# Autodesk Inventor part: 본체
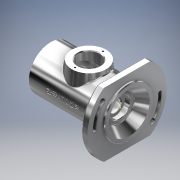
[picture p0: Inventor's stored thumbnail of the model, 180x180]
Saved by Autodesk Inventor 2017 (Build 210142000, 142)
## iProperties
Part Number: 본체
Material: 알루미늄 6061
Document SubType Name: Modeling
Designer: MRC
Density: 2.7 g/cm^3
Appearance: 알루미늄 - 평지
Mass: 686.809 g
Surface Area: 618.883 cm^2
Volume: 254.374 cm^3
Author: MRC
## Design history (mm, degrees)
sketch "스케치1"
  geometry: L1 (47, 33.985)-(47, -33.985); L2 (-47, 33.985)-(-47, -33.985); A1 r 58 centre (0, 0) between (47, 33.985) and (-47, 33.985); A2 r 58 centre (0, 0) between (-47, -33.985) and (47, -33.985); 1 further point
  constraints: 4 end point, 4 point on circle, 2 centre point, 2 vertical, 1 coincident
  dimensions: "d1" = 47 distance from line of point (0, 0) L1; "d2" = 47 distance from line of point (0, 0) L2; "d3" = 58 radius of A2; "d4" = 58 radius of A1
extrude "돌출1" new body sketch "스케치1" distance "d5" = 10; taper "d6" = 0 deg
sketch "스케치2"
  geometry: C1 r 32 at (0, 0); 1 further point
  constraints: 1 centre point, 1 coincident
  dimensions: "d7" = 64 diameter of C1
extrude "돌출2" join sketch "스케치2" distance "d8" = 102; taper "d9" = 0 deg
node "작업 평면1"
sketch "스케치3"
  geometry: L1 (0, 33.985)-(0, -33.985) reference; L2 (102, -32)-(102, 32) reference; C1 r 25 at (46, 0); 2 further points
  constraints: 1 centre point, 1 horizontal alignment, 1 midpoint
  dimensions: "d11" = 50 diameter of C1; "d12" = 56 distance from line of C1.centre L2
extrude "돌출3" join sketch "스케치3" stored distance "d13" = 102; taper "d14" = 5 deg
sketch "스케치4"
  geometry: C1 r 36 at (0, 0); 1 further point
  constraints: 1 centre point, 1 coincident
  dimensions: "d15" = 72 diameter of C1
extrude "돌출4" join sketch "스케치4" distance "d16" = 3; taper "d17" = 0 deg
sketch "스케치5"
  geometry: L1 (-102, 32)-(-102, -32) reference; L2 (-102, 0)-(13, 0); L3 (13, -36)-(13, 36) reference; L4 (-102, 0)-(-102, 22.5); L5 (-102, 22.5)-(-94, 22.5); L6 (-94, 22.5)-(-94, 24); L7 (-94, 24)-(-91, 24); L8 (-91, 24)-(-91, 22.5); L9 (-91, 22.5)-(-80, 22.5); L10 (-80, 22.5)-(-80, 17.5); L11 (-80, 17.5)-(-77.75, 17.5); L12 (-76, 17.5)-(-76, 18.5); L13 (-77.75, 18.5)-(-77.75, 17.5); L14 (-76, 17.5)-(-65, 17.5); L15 (-65, 17.5)-(-65, 27); L16 (-65, 27)-(-27, 27); L17 (-27, 27)-(-27, 17.5); L18 (-27, 17.5)-(-16, 17.5); L19 (-16, 17.5)-(-16, 15); L20 (-16, 15)-(-11, 15); L21 (-11, 15)-(-11, 11); L22 (-11, 11)-(-8.3, 11); L23 (-8.3, 11)-(-8.3, 15); L24 (-1, 15)-(-1, 20); L25 (-1, 20)-(13, 30); L26 (13, 30)-(13, 0); L27 (-76, 18.5)-(-77.75, 18.5); L28 (-8.3, 15)-(-1, 15); 1 further point
  constraints: 52 end point, 15 perpendicular, 5 point on line, 3 horizontal, 2 midpoint, 1 parallel
  dimensions: "d18" = 45 diameter of L5 L2; "d19" = 48 diameter of L7 L2; "d20" = 45 diameter of L9 L2; "d21" = 37 diameter of L27 L2; "d22" = 35 diameter of L11 L2; "d23" = 54 diameter of L16 L2; "d24" = 30 diameter of L20 L2; "d25" = 22 diameter of L22 L2; "d26" = 30 diameter of L28 L2; "d27" = 40 diameter of L24.end L2; "d28" = 60 diameter of L25.end L2; "d29" = 8 distance of L4.end L5.end; "d30" = 3 distance of L6.end L7.end; "d31" = 22 distance between parallel lines of L10 L4; "d33" = 38 distance of L15.end L16.end; "d34" = 11 distance of L17.end L18.end; "d35" = 5 distance of L19.end L20.end; "d36" = 14 horizontal distance of L24.end L25.end; "d38" = 1.75 distance of L12.end L13.start; "d39" = 7.3 distance of L23.end L24.start; "d128" = 4 distance between parallel lines of L12 L10; "d129" = 11 distance of L12.start L14.end; "d130" = 2.25 distance of L10.end L11.end
revolve "회전1" sketch "스케치5" stored, may be unused: angle "d40" = 90 deg
sketch "스케치6"
  geometry: 1 further point
feature "스레드1" dims "d41" = 10, "d42" = 0
sketch "스케치7"
  geometry: C1 r 25 at (0, 0) reference; C2 r 16 at (0, 0); 1 further point
  constraints: 1 centre point, 1 coincident
  dimensions: "d43" = 32 diameter of C2
extrude "돌출5" cut sketch "스케치7" distance "d44" = 30; taper "d45" = 0 deg
sketch "스케치8"
  geometry: L1 (0, 0)-(36.77, 30.854); L2 (0, 0)-(48, 0); L3 (0, 0)-(-36.77, -30.854); A1 r 48 centre (0, 0) between (36.77, 30.854) and (48, 0); A2 r 4 centre (36.77, 30.854) between (40.58, 29.636) and (37.033, 26.862); A3 r 4 centre (-36.77, -30.854) between (-40.58, -29.636) and (-37.033, -26.862); A4 r 2.25 centre (-48, 0) between (-45.75, 0) and (-50.25, 0); A5 r 4 centre (-48, 0) between (-44, 0) and (-52, 0); A6 r 4 centre (48, 0) between (44, 0) and (52, 0); A7 r 2.25 centre (48, 0) between (45.75, 0) and (50.25, 0); A8 r 52 centre (0, 0) between (52, 0) and (39.834, 33.425); A9 r 52 centre (0, 0) between (-52, 0) and (-39.834, -33.425); A10 r 50.25 centre (0, 0) between (50.25, 0) and (40.58, 29.636); A11 r 50.25 centre (0, 0) between (-50.25, 0) and (-40.58, -29.636); A12 r 45.75 centre (0, 0) between (45.75, 0) and (37.033, 26.862); A13 r 45.75 centre (0, 0) between (-45.75, 0) and (-37.033, -26.862); A14 r 44 centre (0, 0) between (44, 0) and (33.706, 28.283); A15 r 44 centre (0, 0) between (-44, 0) and (-33.706, -28.283); 1 further point
  constraints: 36 point on circle, 15 centre point, 6 coincident, 6 end point, 1 collinear, 1 horizontal, 1 horizontal alignment
  dimensions: "d46" = 96 diameter of A1; "d47" = 40 deg angle of L2 L1; "d48" = 8 diameter of A2; "d49" = 8 diameter of A3; "d72" = 4.5 diameter of A4; "d73" = 8 diameter of A5; "d74" = 8 diameter of A6; "d75" = 4.5 diameter of A7; "d76" = 52 radius of A8; "d77" = 50.25 radius of A10; "d78" = 45.75 radius of A12; "d79" = 44 radius of A14; "d80" = 44 radius of A15; "d81" = 45.75 radius of A13; "d82" = 50.25 radius of A11; "d83" = 52 radius of A9
extrude "돌출7" cut sketch "스케치8" distance "d84" = 4.4; taper "d85" = 0 deg
sketch "스케치10"
  geometry: L1 (-58, 0)-(57.839, 0); L2 (36.77, 30.854)-(0, 0); L3 (0, 0)-(-36.77, -30.854); C1 r 4 at (-36.77, -30.854); C2 r 4 at (36.77, 30.854); A1 r 58 centre (0, 0) between (-33.985, 47) and (-33.985, -47) reference; A2 r 48 centre (0, 0) between (-36.77, -30.854) and (36.77, 30.854); 1 further point
  constraints: 6 end point, 3 centre point, 3 point on circle, 1 coincident, 1 horizontal, 1 point on line
  dimensions: "d86" = 8 diameter of C1; "d87" = 8 diameter of C2; "d88" = 40 deg angle of L1 L2; "d89" = 40 deg angle of L1 L3; "d90" = 96 diameter of A2
extrude "돌출8" cut sketch "스케치10" stored distance "d91" = 4.4; taper "d92" = 0 deg
extrude "돌출9" cut sketch "스케치8" stored distance "d93" = 4.4; taper "d94" = 0 deg
sketch "스케치11"
  geometry: C1 r 16 at (0, 0) reference; A1 r 20.5 centre (0, 0) between (0, 20.5) and (0, -20.5); 1 further point
  constraints: 2 point on circle, 2 vertical alignment, 1 centre point, 1 coincident
  dimensions: "d95" = 41 diameter of A1
hole "구멍1" sketch "스케치11" at (0, 20.5), (0, -20.5) diameter "d96" = 2.459; stored, may be unused: countersink angle "d100" = 90 deg, drill point angle "d102" = 118 deg; dims "d97" = 6, "d98" = 4, "d99" = 2, "d101" = 8
fillet "모깎기1" dims "d103" = 3
fillet "모깎기2" dims "d104" = 3
fillet "모깎기3" dims "d105" = 3
fillet "모깎기4" dims "d106" = 3
fillet "모깎기5" dims "d107" = 0.6
fillet "모깎기6" dims "d108" = 0.5
chamfer "모따기1" distance "d109" = 0.7; stored, may be unused: second distance "d110" = 2, angle "d111" = 30 deg
chamfer "모따기2" distance "d112" = 1; stored, may be unused: second distance "d113" = 2, angle "d114" = 30 deg
chamfer "모따기3" distance "d115" = 1; stored, may be unused: second distance "d116" = 2, angle "d117" = 30 deg
chamfer "모따기4" distance "d118" = 1; stored, may be unused: second distance "d119" = 2, angle "d120" = 30 deg
fillet "모깎기7" dims "d121" = 3
fillet "모깎기8" dims "d122" = 3
fillet "모깎기9" dims "d123" = 3
node "작업 평면2"
sketch "스케치12"
  geometry: L1 (10, -46.4)-(10, 46.4) reference; L2 (0, -44)-(0, 44) reference; 3 further points
  constraints: 1 horizontal alignment, 1 midpoint, 1 other
  dimensions: "d125" = 62 distance from line of L1 point (-52, 0)
feature "엠보싱1" sketch "스케치12" dims "d1" = 47, "d2" = 47, "d3" = 58, "d4" = 58, "d126" = 0.5, "d127" = 0
node "솔리드1"
other parameters: "d0" = 116, "d10" = 38, "d53" = 2.25, "d54" = 2.25, "d57" = 4, "d58" = 4, "d60" = 8, "d68" = 4, "d69" = 4, "d70" = 2.25, "d71" = 2.25, "d124" = 42
